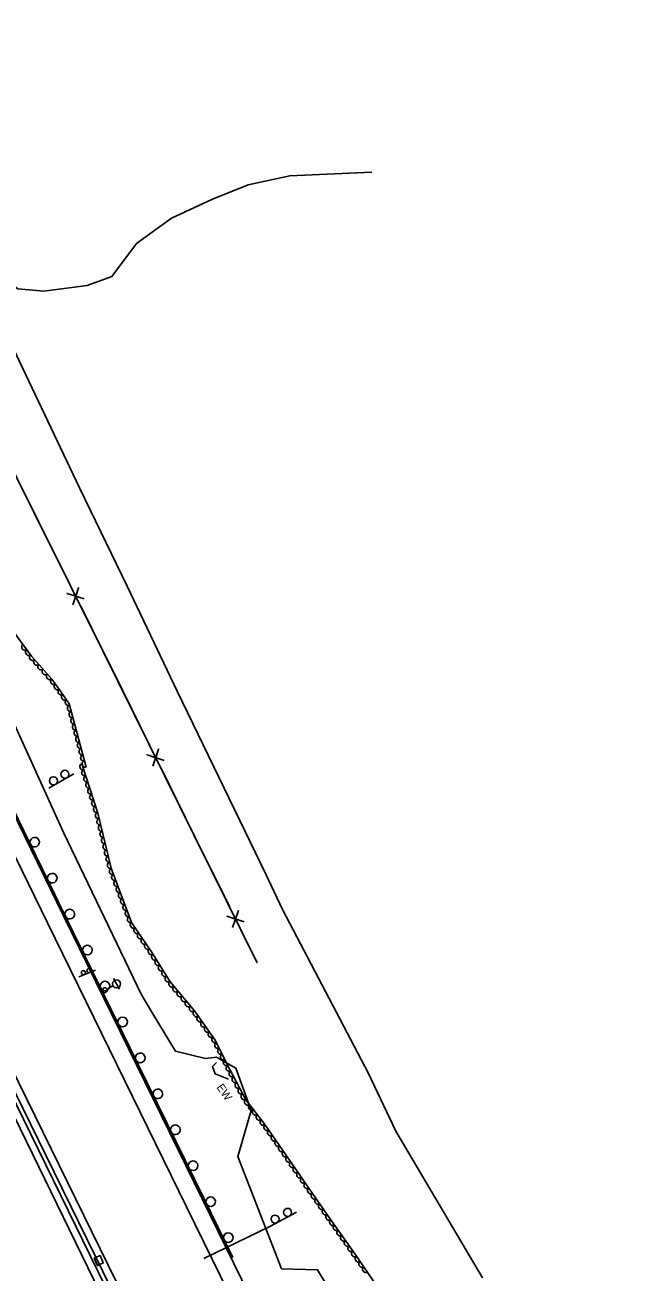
# Model space of a CAD drawing. Extents: x 1746719 to 1766531, y 631721 to 662391.
# Drawn here: x 1763317 to 1763705, y 635506 to 636285 of the extents above; entities that cross this region are included whole.
import ezdxf

# ---------------------------------------------------------------- set-up
doc = ezdxf.new("R2010")
doc.units = 0
for name, color, linetype in [('SURVEY - AERIAL SURVEY - Photo Control - Points - Elevations', 7, 'Continuous'), ('SURVEY - AERIAL SURVEY - Photo Control - Points - Locators', 7, 'Continuous'), ('SURVEY - AERIAL SURVEY - Photo Control - Points - Numbers', 7, 'Continuous'), ('SURVEY - AERIAL SURVEY - Photo Control with Text', 7, 'Continuous'), ('SURVEY - CENTERLINE - Existing Roads - Development', 7, 'Continuous'), ('SURVEY - CENTERLINE - Existing Roads Curve Text', 7, 'Continuous'), ('SURVEY - CENTERLINE - Existing Roads Text', 7, 'Continuous'), ('SURVEY - CENTERLINE - Preliminary - Development', 7, 'Continuous'), ('SURVEY - CENTERLINE - Preliminary Curve Text', 7, 'Continuous'), ('SURVEY - CONTROL - Grid', 7, 'Continuous'), ('SURVEY - CONTROL - Points - Locators', 7, 'Continuous')]:
    doc.layers.add(name, color=color, linetype=linetype)

msp = doc.modelspace()

# ---------------------------------------------------------------- linework, layer by layer
at = {"layer": 'SURVEY - AERIAL SURVEY - Photo Control - Points - Elevations'}
for points in [[(1763695, 634978.85), (1763630.44, 635111.43), (1763562.79, 635249.68), (1763491.57, 635394.79), (1763417.31, 635546.47), (1763330.49, 635723.75), (1763254.01, 635880.59), (1763177.55, 636036.83), (1763112.8, 636168.96), (1763033.11, 636332.35), (1762965.6, 636470.32), (1762837.37, 636731.67)], [(1763704.89, 634983.66), (1763640.33, 635116.26), (1763572.67, 635254.52), (1763501.45, 635399.63), (1763427.19, 635551.31), (1763340.37, 635728.58), (1763263.89, 635885.41), (1763187.43, 636041.67), (1763122.68, 636173.79), (1763042.99, 636337.18), (1762975.48, 636475.16), (1762847.24, 636736.51)], [(1763641.05, 634952.58), (1763576.52, 635085.11), (1763508.91, 635223.28), (1763437.7, 635368.38), (1763363.42, 635520.08), (1763276.58, 635697.4), (1763200.09, 635854.25), (1763123.66, 636010.44), (1763058.89, 636142.6), (1762979.2, 636306.01), (1762911.72, 636443.92), (1762783.5, 636705.24)], [(1762773.06, 636698.72), (1762814.67, 636613.42), (1762883.84, 636472.89), (1762954.11, 636329.07), (1763023.11, 636188.11), (1763074.26, 636083.06), (1763161.07, 635905.77), (1763211.77, 635802.95), (1763267.45, 635689.5), (1763370.88, 635477.29), (1763451.14, 635313.44)]]:
    msp.add_lwpolyline(points, dxfattribs=at)
at = {"layer": 'SURVEY - AERIAL SURVEY - Photo Control - Points - Locators'}
for points in [[(1762855.72, 636761.66), (1762915.79, 636794.06), (1762948.96, 636813.36), (1762952.81, 636806.93), (1763013.9, 636685.45), (1763025.09, 636662.89), (1763070.4, 636555.62), (1763094.41, 636499.13), (1763123.77, 636445.46), (1763150.07, 636397.69), (1763162.17, 636366.06), (1763198.22, 636302.04), (1763238.5, 636231.32), (1763273.29, 636158.17), (1763313.15, 636074.51), (1763350.67, 635995.46), (1763380.26, 635934.07), (1763411.62, 635868.46), (1763466.91, 635754.2), (1763477.33, 635732.13), (1763497.46, 635693.59), (1763531.02, 635629.76), (1763548.12, 635593.75), (1763602.09, 635502.11)], [(1763534.47, 635448.54), (1763499.23, 635506.99), (1763476.71, 635507.76), (1763449.36, 635577.9), (1763457.64, 635606.63), (1763448.2, 635633.11), (1763436.18, 635639.91), (1763429.18, 635639.1), (1763410.49, 635643.7), (1763396.42, 635667.02), (1763389.12, 635679.24), (1763340.83, 635779.81), (1763290.46, 635890.46)]]:
    msp.add_lwpolyline(points, dxfattribs=at)
at = {"layer": 'SURVEY - AERIAL SURVEY - Photo Control - Points - Numbers'}
msp.add_line((1763469.4, 635534.19), (1763428.23, 635514.04), dxfattribs=at)
for points in [[(1763446.24, 635514.67), (1763428.09, 635551.75), (1763341.27, 635729.02), (1763264.79, 635885.85), (1763188.33, 636042.11), (1763123.58, 636174.23), (1763043.89, 636337.61), (1762976.38, 636475.6), (1762848.14, 636736.95)], [(1763635.49, 634947.88), (1763550.57, 635121.13), (1763412.96, 635402), (1763296.92, 635639.14), (1763179.78, 635878.6), (1763016.73, 636211.43), (1762900.31, 636449.87), (1762810.07, 636633.97), (1762777.65, 636700.23)], [(1762780.33, 636702.09), (1762833.11, 636593.25), (1762910.17, 636436.51), (1763005.6, 636241.46), (1763118.37, 636010.26), (1763219.08, 635804.06), (1763329.74, 635578.22), (1763441.15, 635350.94), (1763538.42, 635152.66), (1763637.77, 634949.46)], [(1763321.88, 635768.77), (1763317.85, 635777.04)], [(1763325.34, 635761.67), (1763323.29, 635765.9)], [(1763327.41, 635757.45), (1763325.34, 635761.67)], [(1763332.84, 635746.3), (1763328.81, 635754.57)], [(1763336.3, 635739.2), (1763334.24, 635743.43)], [(1763338.36, 635734.98), (1763336.3, 635739.2)], [(1763343.81, 635723.84), (1763341.27, 635729.02), (1763339.77, 635732.1)], [(1763347.28, 635716.74), (1763345.21, 635720.96)], [(1763349.35, 635712.52), (1763347.28, 635716.74)], [(1763354.8, 635701.38), (1763350.76, 635709.65)], [(1763358.28, 635694.29), (1763356.21, 635698.51)], [(1763360.34, 635690.07), (1763358.28, 635694.29)], [(1763365.8, 635678.93), (1763361.75, 635687.19)], [(1763369.27, 635671.84), (1763367.21, 635676.06)], [(1763371.34, 635667.62), (1763369.27, 635671.84)], [(1763376.79, 635656.48), (1763372.75, 635664.74)], [(1763380.27, 635649.39), (1763378.2, 635653.61)], [(1763382.34, 635645.16), (1763380.27, 635649.39)], [(1763387.79, 635634.03), (1763383.74, 635642.29)], [(1763391.27, 635626.93), (1763389.2, 635631.15)], [(1763393.33, 635622.71), (1763391.27, 635626.93)], [(1763398.79, 635611.58), (1763394.74, 635619.84)], [(1763402.26, 635604.48), (1763400.19, 635608.7)], [(1763404.33, 635600.26), (1763402.26, 635604.48)], [(1763409.78, 635589.12), (1763405.74, 635597.39)], [(1763413.26, 635582.03), (1763411.19, 635586.25)], [(1763415.32, 635577.81), (1763413.26, 635582.03)], [(1763420.78, 635566.67), (1763416.73, 635574.93)], [(1763424.25, 635559.58), (1763422.19, 635563.8)], [(1763426.32, 635555.36), (1763424.25, 635559.58)], [(1763431.77, 635544.22), (1763428.09, 635551.75), (1763427.73, 635552.48)], [(1763435.25, 635537.12), (1763433.18, 635541.35)], [(1763437.31, 635532.9), (1763435.25, 635537.12)], [(1763442.77, 635521.77), (1763438.72, 635530.03)], [(1763446.24, 635514.67), (1763444.17, 635518.89)]]:
    msp.add_lwpolyline(points, dxfattribs=at)
for centre, start, end in [((1763322.58, 635774.18), 319.2644, 319.25041), ((1763333.54, 635751.71), 319.2644, 319.25041), ((1763344.5, 635729.25), 319.36207, 319.34808), ((1763355.49, 635706.79), 319.36207, 319.34808), ((1763366.49, 635684.34), 319.36207, 319.34808), ((1763377.48, 635661.89), 319.36207, 319.34808), ((1763388.48, 635639.44), 319.36207, 319.34808), ((1763399.48, 635616.99), 319.36207, 319.34808), ((1763410.47, 635594.53), 319.36207, 319.34808), ((1763421.47, 635572.08), 319.36207, 319.34808), ((1763432.46, 635549.63), 319.35388, 319.33989), ((1763443.46, 635527.18), 319.35388, 319.33989)]:
    msp.add_arc(centre, 3, start, end, dxfattribs=at)
at = {"layer": 'SURVEY - AERIAL SURVEY - Photo Control with Text'}
for points in [[(1763354.68, 635821.06), (1763344.17, 635860.62), (1763338.79, 635868.53), (1763333.29, 635876.08), (1763320.53, 635890.36), (1763306.77, 635909.11)], [(1763536.92, 635496.09), (1763521.53, 635518.35), (1763506.85, 635539.19), (1763492.38, 635560.13), (1763475.3, 635584.86), (1763465.32, 635599.24), (1763454.41, 635613.25), (1763442.61, 635635.73), (1763435.3, 635650.56), (1763422.28, 635668.81), (1763407.07, 635686.93), (1763395.48, 635705.69), (1763383.08, 635723.99), (1763370.38, 635757.9), (1763362, 635792.3), (1763352.12, 635823.04)]]:
    msp.add_lwpolyline(points, dxfattribs=at)
for centre, major_axis in [((1763316.39, 635896.01), (-1.18, 1.61)), ((1763318.75, 635892.79), (-1.18, 1.61)), ((1763321.19, 635889.62), (-1.33, 1.49)), ((1763323.86, 635886.64), (-1.33, 1.49)), ((1763326.53, 635883.66), (-1.33, 1.49)), ((1763329.19, 635880.67), (-1.33, 1.49)), ((1763331.86, 635877.69), (-1.33, 1.49)), ((1763334.38, 635874.59), (-1.18, 1.62)), ((1763336.73, 635871.36), (-1.18, 1.62)), ((1763339.07, 635868.12), (-1.12, 1.65)), ((1763341.32, 635864.81), (-1.12, 1.65)), ((1763343.57, 635861.5), (-1.12, 1.65)), ((1763344.92, 635857.78), (-0.51, 1.93)), ((1763345.95, 635853.91), (-0.51, 1.93)), ((1763346.97, 635850.05), (-0.51, 1.93)), ((1763348, 635846.18), (-0.51, 1.93)), ((1763349.03, 635842.32), (-0.51, 1.93)), ((1763350.06, 635838.45), (-0.51, 1.93)), ((1763351.08, 635834.59), (-0.51, 1.93)), ((1763352.11, 635830.72), (-0.51, 1.93)), ((1763353.14, 635826.85), (-0.51, 1.93)), ((1763352.67, 635821.32), (-0.61, 1.9)), ((1763353.9, 635817.51), (-0.61, 1.9)), ((1763354.16, 635822.99), (-0.51, 1.93)), ((1763355.12, 635813.7), (-0.61, 1.9)), ((1763356.34, 635809.89), (-0.61, 1.9)), ((1763357.57, 635806.09), (-0.61, 1.9)), ((1763358.79, 635802.28), (-0.61, 1.9)), ((1763360.02, 635798.47), (-0.61, 1.9)), ((1763361.24, 635794.66), (-0.61, 1.9)), ((1763362.36, 635790.82), (-0.47, 1.94)), ((1763363.31, 635786.94), (-0.47, 1.94)), ((1763364.25, 635783.05), (-0.47, 1.94)), ((1763365.2, 635779.16), (-0.47, 1.94)), ((1763366.15, 635775.28), (-0.47, 1.94)), ((1763367.09, 635771.39), (-0.47, 1.94)), ((1763368.04, 635767.5), (-0.47, 1.94)), ((1763368.98, 635763.62), (-0.47, 1.94)), ((1763369.93, 635759.73), (-0.47, 1.94)), ((1763371.12, 635755.92), (-0.7, 1.87)), ((1763372.52, 635752.17), (-0.7, 1.87)), ((1763373.92, 635748.43), (-0.7, 1.87)), ((1763375.33, 635744.68), (-0.7, 1.87)), ((1763376.73, 635740.94), (-0.7, 1.87)), ((1763378.13, 635737.19), (-0.7, 1.87)), ((1763379.54, 635733.44), (-0.7, 1.87)), ((1763380.94, 635729.7), (-0.7, 1.87)), ((1763382.34, 635725.95), (-0.7, 1.87)), ((1763384.15, 635722.41), (-1.12, 1.66)), ((1763386.39, 635719.1), (-1.12, 1.66)), ((1763388.63, 635715.79), (-1.12, 1.66)), ((1763390.88, 635712.48), (-1.12, 1.66)), ((1763393.12, 635709.17), (-1.12, 1.66)), ((1763395.37, 635705.86), (-1.12, 1.66)), ((1763397.48, 635702.46), (-1.05, 1.7)), ((1763399.58, 635699.06), (-1.05, 1.7)), ((1763401.68, 635695.65), (-1.05, 1.7)), ((1763403.78, 635692.25), (-1.05, 1.7)), ((1763405.89, 635688.85), (-1.05, 1.7)), ((1763408.19, 635685.59), (-1.29, 1.53)), ((1763410.77, 635682.53), (-1.29, 1.53)), ((1763413.34, 635679.47), (-1.29, 1.53)), ((1763415.91, 635676.4), (-1.29, 1.53)), ((1763418.48, 635673.34), (-1.29, 1.53)), ((1763421.05, 635670.27), (-1.29, 1.53)), ((1763423.49, 635667.11), (-1.16, 1.63)), ((1763425.82, 635663.85), (-1.16, 1.63)), ((1763428.14, 635660.6), (-1.16, 1.63)), ((1763430.46, 635657.34), (-1.16, 1.63)), ((1763432.79, 635654.09), (-1.16, 1.63)), ((1763435.11, 635650.83), (-1.16, 1.63)), ((1763436.93, 635647.27), (-0.88, 1.79)), ((1763438.69, 635643.68), (-0.88, 1.79)), ((1763440.46, 635640.09), (-0.88, 1.79)), ((1763442.23, 635636.51), (-0.88, 1.79)), ((1763444.07, 635632.95), (-0.93, 1.77)), ((1763445.93, 635629.41), (-0.93, 1.77)), ((1763447.79, 635625.87), (-0.93, 1.77)), ((1763449.64, 635622.33), (-0.93, 1.77)), ((1763451.5, 635618.79), (-0.93, 1.77)), ((1763453.36, 635615.24), (-0.93, 1.77)), ((1763455.48, 635611.87), (-1.23, 1.58)), ((1763457.94, 635608.71), (-1.23, 1.58)), ((1763460.4, 635605.56), (-1.23, 1.58)), ((1763462.86, 635602.4), (-1.23, 1.58)), ((1763465.31, 635599.25), (-1.23, 1.58)), ((1763467.6, 635595.96), (-1.14, 1.64)), ((1763469.88, 635592.68), (-1.14, 1.64)), ((1763472.16, 635589.39), (-1.14, 1.64)), ((1763474.44, 635586.11), (-1.14, 1.64)), ((1763476.72, 635582.82), (-1.14, 1.65)), ((1763478.99, 635579.53), (-1.14, 1.65)), ((1763481.26, 635576.23), (-1.14, 1.65)), ((1763483.53, 635572.94), (-1.14, 1.65)), ((1763485.81, 635569.65), (-1.14, 1.65)), ((1763488.08, 635566.36), (-1.14, 1.65)), ((1763490.35, 635563.07), (-1.14, 1.65)), ((1763492.63, 635559.78), (-1.14, 1.65)), ((1763494.9, 635556.49), (-1.14, 1.65)), ((1763497.17, 635553.19), (-1.14, 1.65)), ((1763499.45, 635549.9), (-1.14, 1.65)), ((1763501.72, 635546.61), (-1.14, 1.65)), ((1763504, 635543.32), (-1.14, 1.65)), ((1763506.27, 635540.03), (-1.14, 1.65)), ((1763508.57, 635536.76), (-1.15, 1.64)), ((1763510.87, 635533.49), (-1.15, 1.64)), ((1763513.17, 635530.22), (-1.15, 1.64)), ((1763515.48, 635526.95), (-1.15, 1.64)), ((1763517.78, 635523.68), (-1.15, 1.64)), ((1763520.08, 635520.41), (-1.15, 1.64)), ((1763522.38, 635517.13), (-1.14, 1.65)), ((1763524.65, 635513.84), (-1.14, 1.65)), ((1763526.93, 635510.55), (-1.14, 1.65)), ((1763529.2, 635507.26), (-1.14, 1.65))]:
    msp.add_ellipse(centre, major_axis=major_axis, ratio=0.940188, start_param=0, end_param=3.141593, dxfattribs=at)
at = {"layer": 'SURVEY - CENTERLINE - Existing Roads - Development'}
for p, q in [((1763373.67, 635685.66), (1763371.89, 635688.95)), ((1763367.74, 635682.44), (1763371.47, 635684.47)), ((1763373.67, 635685.66), (1763375.46, 635682.36))]:
    msp.add_line(p, q, dxfattribs=at)
for centre, radius in [((1763373.67, 635685.66), 2.5), ((1763366.42, 635681.73), 1.5)]:
    msp.add_circle(centre, radius, dxfattribs=at)
at = {"layer": 'SURVEY - CENTERLINE - Existing Roads Curve Text'}
for points in [[(1762928.82, 636789.81), (1762960.97, 636723.74), (1763086.1, 636454.87), (1763365.02, 635894.2), (1763461.56, 635698.81)], [(1763301.48, 636021.92), (1763322.14, 635980.38)], [(1763322.14, 635980.38), (1763344.41, 635935.61)], [(1763353.52, 635926.07), (1763342.84, 635929.58), (1763348.2, 635927.78), (1763350, 635933.14), (1763346.35, 635922.51)], [(1763351.58, 635921.2), (1763365.02, 635894.2), (1763372.21, 635879.64)], [(1763372.21, 635879.64), (1763394.36, 635834.81)], [(1763403.44, 635825.24), (1763392.77, 635828.78), (1763398.12, 635826.96), (1763399.94, 635832.32), (1763396.27, 635821.7)], [(1763401.49, 635820.38), (1763422.04, 635778.78)], [(1763422.04, 635778.78), (1763444.19, 635733.95)], [(1763453.27, 635724.38), (1763442.6, 635727.92), (1763447.96, 635726.1), (1763449.77, 635731.46), (1763446.1, 635720.84)], [(1763451.32, 635719.51), (1763461.56, 635698.81)]]:
    msp.add_lwpolyline(points, dxfattribs=at)
at = {"layer": 'SURVEY - CENTERLINE - Existing Roads Text'}
msp.add_lwpolyline([(1763436.03, 635636.63), (1763433.61, 635634), (1763435.25, 635629.58), (1763443.64, 635626.09)], dxfattribs=at)
at = {"layer": 'SURVEY - CENTERLINE - Preliminary Curve Text'}
msp.add_line((1763362.6, 635512.81), (1763362.6, 635512.81), dxfattribs=at)
msp.add_lwpolyline([(1763359.77, 635514.3), (1763363.43, 635515.91), (1763365.44, 635511.33), (1763361.78, 635509.72), (1763359.77, 635514.3)], dxfattribs=at)
at = {"layer": 'SURVEY - CONTROL - Grid'}
for p, q in [((1763346.94, 635816.85), (1763331.33, 635807.88)), ((1763334.33, 635812.49), (1763334.33, 635812.49)), ((1763334.33, 635812.49), (1763334.33, 635812.49)), ((1763341.45, 635816.58), (1763341.45, 635816.58)), ((1763341.45, 635816.58), (1763341.45, 635816.58)), ((1763360.48, 635694.23), (1763350.05, 635690.16)), ((1763469.4, 635534.19), (1763486.09, 635543.08)), ((1763480.5, 635542.94), (1763480.5, 635542.94)), ((1763480.5, 635542.94), (1763480.5, 635542.94)), ((1763472.63, 635538.75), (1763472.63, 635538.75)), ((1763472.63, 635538.75), (1763472.63, 635538.75))]:
    msp.add_line(p, q, dxfattribs=at)
for centre, radius in [((1763334.33, 635812.51), 2.5), ((1763334.33, 635812.51), 2.5), ((1763341.45, 635816.6), 2.5), ((1763341.45, 635816.6), 2.5), ((1763356.47, 635693.98), 1.25), ((1763352.98, 635692.62), 1.25), ((1763472.64, 635538.77), 2.5), ((1763472.64, 635538.77), 2.5), ((1763480.5, 635542.96), 2.5), ((1763480.5, 635542.96), 2.5)]:
    msp.add_circle(centre, radius, dxfattribs=at)
at = {"layer": 'SURVEY - CONTROL - Points - Locators'}
msp.add_lwpolyline([(1762681.93, 636283.35), (1762763.42, 636255.94), (1762832.62, 636242.35), (1762876.46, 636236.07), (1763176.38, 636206.61), (1763187.73, 636201.48), (1763216.94, 636186.87), (1763287.75, 636137.92), (1763312.14, 636119.77), (1763328.27, 636118.25), (1763355.3, 636121.86), (1763370.77, 636127.57), (1763386.19, 636148.02), (1763407.97, 636163.97), (1763433.5, 636175.78), (1763455.92, 636184.72), (1763481.97, 636190.29), (1763533.13, 636192.58)], dxfattribs=at)

# ---------------------------------------------------------------- texts
at = {"layer": 'SURVEY - CENTERLINE - Preliminary - Development'}
msp.add_text('EW', height=5, rotation=304.64647, dxfattribs=at).set_placement((1763435.89, 635621.08))

doc.saveas('drawing.dxf')
